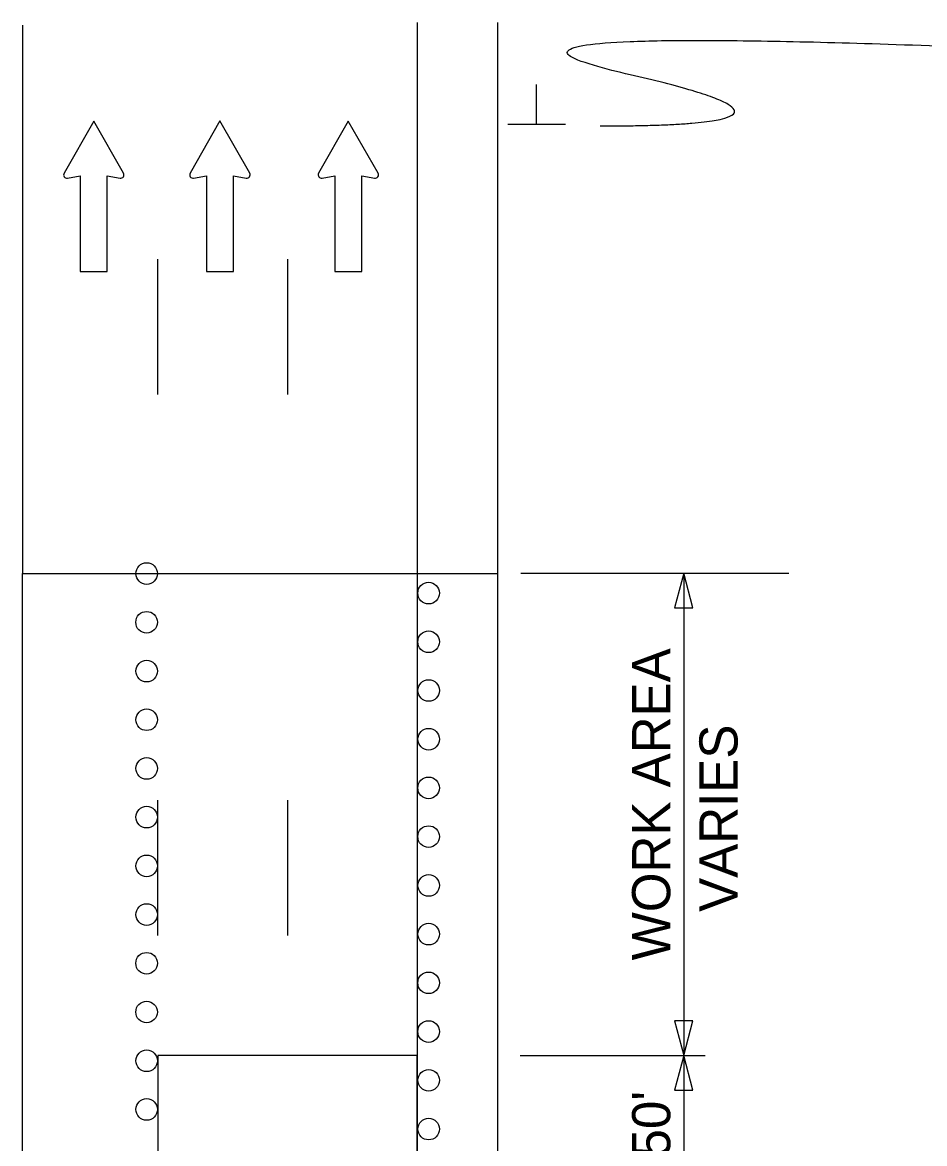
# Model space of a CAD drawing. Extents: x -1809 to 1557, y -1087 to 44.
# Drawn here: x -1476.9 to -1310.2, y -167 to 40.1 of the extents above; entities that cross this region are included whole.
import ezdxf

# ---------------------------------------------------------------- set-up
doc = ezdxf.new("R2010")
doc.units = 0
for name, color, linetype in [('BORDER', 7, 'Continuous'), ('MT_SCRATCH_LEVEL_A', 7, 'Continuous'), ('MT_SCRATCH_LEVEL_E', 7, 'Continuous'), ('MT_STAGE_1A_NOTES', 7, 'Continuous'), ('PAVT_EDGE_EX', 7, 'Continuous'), ('TRAFFIC_SIGNS_PR', 7, 'Continuous'), ('TYPICAL_EX', 7, 'Continuous'), ('TYPICAL_TEXT_DIMEN_PR', 7, 'Continuous')]:
    doc.layers.add(name, color=color, linetype=linetype)

msp = doc.modelspace()

# ---------------------------------------------------------------- linework, layer by layer
at = {"layer": 'BORDER'}
for p, q in [((-1403.94, 40.09), (-1403.94, -150.77)), ((-1451.94, -3.63), (-1451.94, -28.63)), ((-1427.94, -3.63), (-1427.94, -28.63)), ((-1451.94, -103.63), (-1451.94, -128.63)), ((-1427.94, -103.63), (-1427.94, -128.63)), ((-1403.94, -150.77), (-1403.94, -403.06))]:
    msp.add_line(p, q, dxfattribs=at)
at = {"layer": 'MT_SCRATCH_LEVEL_A'}
msp.add_line((-1476.89, 39.56), (-1476.89, -61.73), dxfattribs=at)
msp.add_lwpolyline([(-1476.89, -61.73), (-1389.15, -61.73), (-1389.15, -240.97), (-1403.94, -240.97), (-1403.94, -150.77), (-1451.85, -150.77), (-1451.94, -376.78), (-1476.89, -376.78), (-1476.89, -61.73), (-1476.89, -61.73)], close=True, dxfattribs=at)
at = {"layer": 'MT_SCRATCH_LEVEL_E'}
for p, q in [((-1463.73, 21.87), (-1469.21, 12.22)), ((-1458.2, 12.22), (-1463.73, 21.87)), ((-1440.43, 21.9), (-1445.91, 12.24)), ((-1434.9, 12.24), (-1440.43, 21.9)), ((-1416.69, 21.87), (-1422.17, 12.22)), ((-1411.16, 12.22), (-1416.69, 21.87)), ((-1468.57, 11.3), (-1466.2, 11.72)), ((-1466.2, 11.72), (-1466.2, -5.95)), ((-1461.21, -5.95), (-1461.21, 11.72)), ((-1461.21, 11.72), (-1458.84, 11.3)), ((-1445.27, 11.33), (-1442.9, 11.75)), ((-1442.9, 11.75), (-1442.9, -5.93)), ((-1437.91, -5.93), (-1437.91, 11.75)), ((-1437.91, 11.75), (-1435.54, 11.33)), ((-1421.53, 11.3), (-1419.16, 11.72)), ((-1419.16, 11.72), (-1419.16, -5.95)), ((-1414.17, -5.95), (-1414.17, 11.72)), ((-1414.17, 11.72), (-1411.8, 11.3)), ((-1466.2, -5.95), (-1461.21, -5.95)), ((-1442.9, -5.93), (-1437.91, -5.93)), ((-1419.16, -5.95), (-1414.17, -5.95))]:
    msp.add_line(p, q, dxfattribs=at)
for centre, start, end in [((-1468.67, 11.92), 150.4248, 279.9638), ((-1458.75, 11.92), 260.0362, 29.7731), ((-1445.37, 11.94), 150.4248, 279.9638), ((-1435.44, 11.94), 260.0362, 29.7731), ((-1421.63, 11.92), 150.4248, 279.9638), ((-1411.71, 11.92), 260.0362, 29.7731)]:
    msp.add_arc(centre, 0.617, start, end, dxfattribs=at)
at = {"layer": 'MT_STAGE_1A_NOTES'}
for p, q in [((-1384.82, -61.68), (-1335.29, -61.68)), ((-1354.71, -61.78), (-1354.71, -253.81)), ((-1384.95, -150.77), (-1350.78, -150.77))]:
    msp.add_line(p, q, dxfattribs=at)
msp.add_open_spline([(-1370.17, 20.96), (-1323.04, 20.96), (-1407.58, 40.22), (-1285.69, 34.85)], degree=2, dxfattribs=at)
at = {"layer": 'PAVT_EDGE_EX'}
for p, q in [((-1389.15, 40.09), (-1389.15, -150.83)), ((-1389.15, -150.83), (-1389.15, -407))]:
    msp.add_line(p, q, dxfattribs=at)
at = {"layer": 'TRAFFIC_SIGNS_PR'}
for centre in [(-1453.94, -61.74), (-1401.85, -65.34), (-1453.95, -70.74), (-1401.85, -74.34), (-1453.94, -79.75), (-1401.84, -83.34), (-1453.94, -88.74), (-1401.84, -92.34), (-1453.94, -97.74), (-1401.85, -101.34), (-1453.94, -106.74), (-1401.85, -110.34), (-1453.94, -115.75), (-1401.84, -119.35), (-1453.94, -124.74), (-1401.84, -128.35), (-1453.95, -133.74), (-1401.85, -137.35), (-1453.95, -142.74), (-1401.85, -146.35), (-1453.94, -151.75), (-1401.84, -155.36), (-1453.94, -160.74), (-1401.84, -164.36)]:
    msp.add_circle(centre, 2, dxfattribs=at)
at = {"layer": 'TYPICAL_EX'}
for p, q in [((-1381.9, 21.23), (-1381.9, 28.63)), ((-1381.9, 21.23), (-1387.24, 21.23)), ((-1376.55, 21.23), (-1381.9, 21.23)), ((-1476.89, -61.73), (-1408.49, -61.73)), ((-1408.47, -61.73), (-1389.15, -61.73))]:
    msp.add_line(p, q, dxfattribs=at)
at = {"layer": 'TYPICAL_TEXT_DIMEN_PR'}
for p, q in [((-1354.71, -61.68), (-1356.4, -68.09)), ((-1353.01, -68.09), (-1354.71, -61.68)), ((-1356.4, -68.09), (-1354.71, -68.09)), ((-1354.71, -68.09), (-1353.01, -68.09)), ((-1354.71, -144.37), (-1356.4, -144.37)), ((-1356.4, -144.37), (-1354.71, -150.77)), ((-1354.71, -150.77), (-1353.01, -144.37)), ((-1353.01, -144.37), (-1354.71, -144.37)), ((-1354.71, -150.77), (-1356.4, -157.18)), ((-1353.01, -157.18), (-1354.71, -150.77)), ((-1356.4, -157.18), (-1354.71, -157.18)), ((-1354.71, -157.18), (-1353.01, -157.18))]:
    msp.add_line(p, q, dxfattribs=at)

# ---------------------------------------------------------------- texts
at = {"layer": 'MT_STAGE_1A_NOTES'}
for s, p in [('WORK AREA', (-1357.21, -133.2)), ('VARIES', (-1344.77, -124.24)), ("250'", (-1357.2, -174.86))]:
    msp.add_text(s, height=7.054, rotation=90, dxfattribs=at).set_placement(p)

doc.saveas('drawing.dxf')
